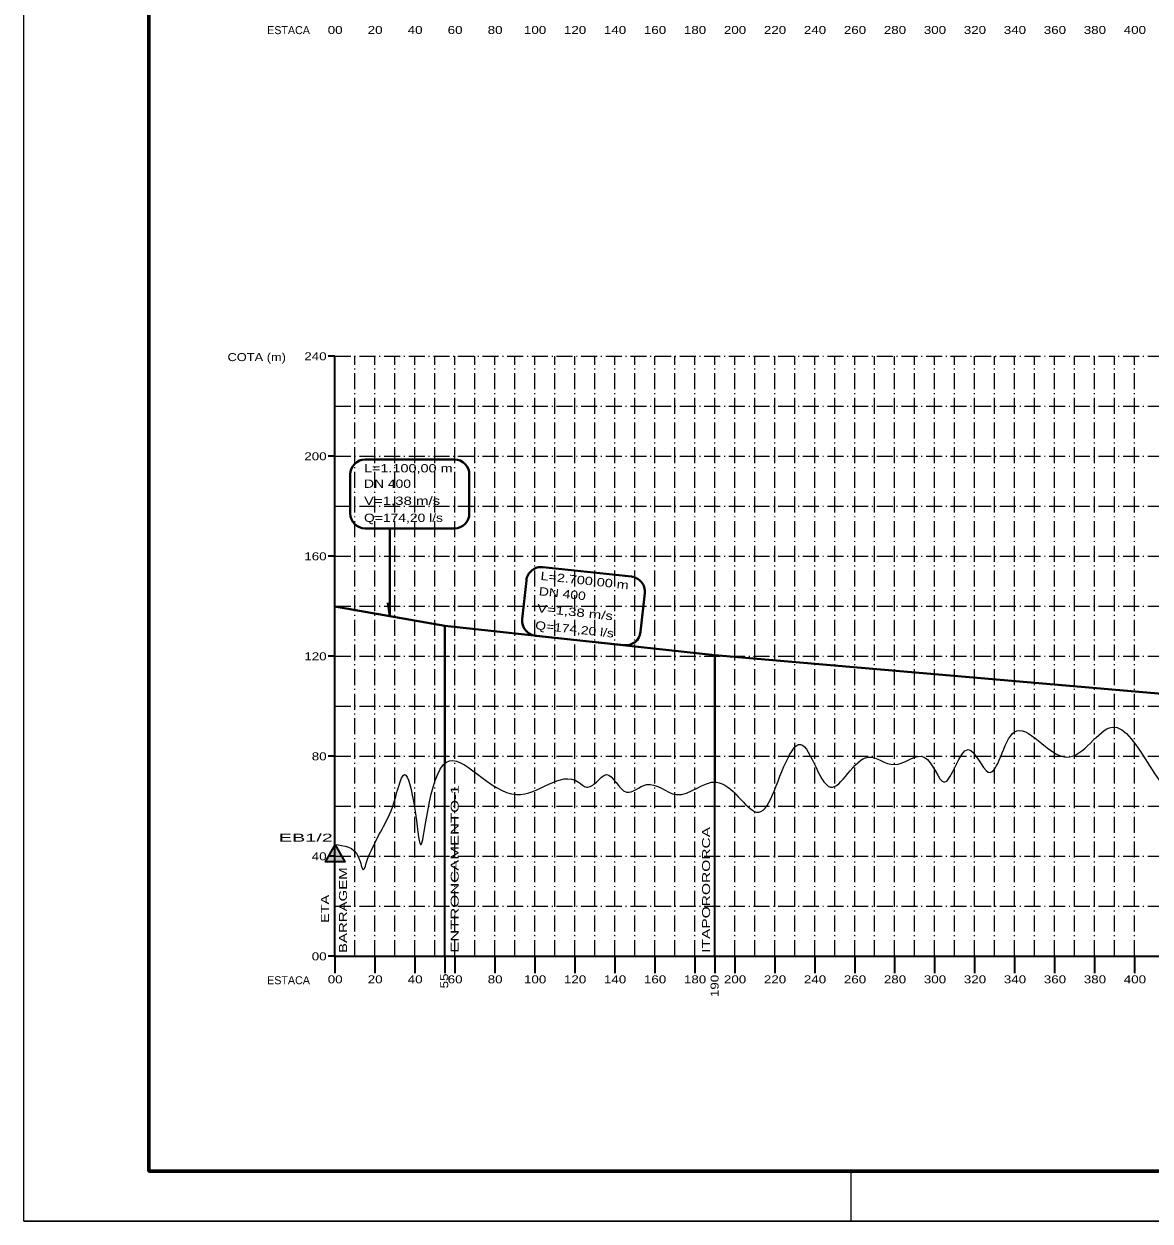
# Model space of a CAD drawing. Extents: x -4 to 42046, y -3 to 29697.
# Drawn here: x -4 to 11261, y -3 to 11967 of the extents above; entities that cross this region are included whole.
import ezdxf
from ezdxf.enums import TextEntityAlignment as Align

# ---------------------------------------------------------------- set-up
doc = ezdxf.new("R2010")
doc.units = 0
doc.header["$LTSCALE"] = 32
doc.linetypes.add('DOT_DASHED', pattern=[7.7, 5, -1.2, 0.3, -1.2])
for name, color, linetype, lineweight in [('1', 7, 'DOT_DASHED', 13), ('24', 7, 'Continuous', 35), ('56', 7, 'Continuous', 13), ('62', 7, 'Continuous', 13), ('63', 7, 'Continuous', 25), ('9', 7, 'Continuous', 40)]:
    doc.layers.add(name, color=color, linetype=linetype, lineweight=lineweight)

msp = doc.modelspace()

# ---------------------------------------------------------------- hatches: boundary and pattern name
at = {"layer": '62'}
msp.add_hatch(color=256, dxfattribs=at).paths.add_polyline_path([(3107.85, 3758.2), (3206.51, 3589.75), (3011.3, 3588.54)])

# ---------------------------------------------------------------- linework, layer by layer
at = {"layer": '1'}
for p, q in [((3105.77, 8646.17), (29145.77, 8646.17)), ((3305.77, 2646.17), (3305.77, 8646.17)), ((3505.77, 2646.17), (3505.77, 8646.17)), ((3705.77, 2646.17), (3705.77, 8646.17)), ((3905.77, 2646.17), (3905.77, 8646.17)), ((4105.77, 2646.17), (4105.77, 8646.17)), ((4305.77, 2646.17), (4305.77, 8646.17)), ((4505.77, 2646.17), (4505.77, 8646.17)), ((4705.77, 2646.17), (4705.77, 8646.17)), ((4905.77, 2646.17), (4905.77, 8646.17)), ((5105.77, 2646.17), (5105.77, 8646.17)), ((5305.77, 2646.17), (5305.77, 8646.17)), ((5505.77, 2646.17), (5505.77, 8646.17)), ((5705.77, 2646.17), (5705.77, 8646.17)), ((5905.77, 2646.17), (5905.77, 8646.17)), ((6105.77, 2646.17), (6105.77, 8646.17)), ((6305.77, 2646.17), (6305.77, 8646.17)), ((6505.77, 2646.17), (6505.77, 8646.17)), ((6705.77, 2646.17), (6705.77, 8646.17)), ((6905.77, 2646.17), (6905.77, 8646.17)), ((7105.77, 2646.17), (7105.77, 8646.17)), ((7305.77, 2646.17), (7305.77, 8646.17)), ((7505.77, 2646.17), (7505.77, 8646.17)), ((7705.77, 2646.17), (7705.77, 8646.17)), ((7905.77, 2646.17), (7905.77, 8646.17)), ((8105.77, 2646.17), (8105.77, 8646.17)), ((8305.77, 2646.17), (8305.77, 8646.17)), ((8505.77, 2646.17), (8505.77, 8646.17)), ((8705.77, 2646.17), (8705.77, 8646.17)), ((8905.77, 2646.17), (8905.77, 8646.17)), ((9105.77, 2646.17), (9105.77, 8646.17)), ((9305.77, 2646.17), (9305.77, 8646.17)), ((9505.77, 2646.17), (9505.77, 8646.17)), ((9705.77, 2646.17), (9705.77, 8646.17)), ((9905.77, 2646.17), (9905.77, 8646.17)), ((10105.77, 2646.17), (10105.77, 8646.17)), ((10305.77, 2646.17), (10305.77, 8646.17)), ((10505.77, 2646.17), (10505.77, 8646.17)), ((10705.77, 2646.17), (10705.77, 8646.17)), ((10905.77, 2646.17), (10905.77, 8646.17)), ((11105.77, 2646.17), (11105.77, 8646.17)), ((3105.77, 8146.17), (29145.77, 8146.17)), ((3105.77, 7646.17), (29145.77, 7646.17)), ((3105.77, 7146.17), (29145.77, 7146.17)), ((3105.77, 6646.17), (29145.77, 6646.17)), ((3105.77, 6146.17), (29145.77, 6146.17)), ((3105.77, 5646.17), (29145.77, 5646.17)), ((3105.77, 5146.17), (29145.77, 5146.17)), ((3105.77, 4646.17), (29145.77, 4646.17)), ((3105.77, 4146.17), (29145.77, 4146.17)), ((3105.77, 3646.17), (29145.77, 3646.17)), ((3105.77, 3146.17), (29145.77, 3146.17))]:
    msp.add_line(p, q, dxfattribs=at)
at = {"layer": '56'}
for points in [[(3442.18, 3641.64), (3562.37, 3886.04), (3682.37, 4136.04), (3802.37, 4461.04), (3902.37, 4136.04), (3962.37, 3761.04), (4222.37, 4586.04), (4922.37, 4261.04), (5542.37, 4386.04), (5622.37, 4336.04), (5722.37, 4386.04), (5822.37, 4461.04), (6022.37, 4286.04), (6222.37, 4361.04), (6522.37, 4261.04), (6922.37, 4386.04), (7322.37, 4086.04), (7642.37, 4636.04), (7742.37, 4761.04), (8062.37, 4336.04), (8442.37, 4636.04), (8702.37, 4561.04), (9002.37, 4636.04), (9202.37, 4386.04), (9442.37, 4711.04), (9642.37, 4486.04), (9902.37, 4886.04), (10422.37, 4636.04), (10882.37, 4936.04), (11642.37, 4261.04), (11942.37, 4511.04), (12062.37, 4386.04), (12382.37, 4411.04), (12982.37, 3611.04), (13192.37, 3711.04), (13592.37, 3636.04), (14032.37, 4011.04), (14532.37, 4661.04), (14732.37, 4386.04), (15932.37, 3461.04), (16672.37, 4386.04), (17705.77, 4596.17), (19279.94, 4205.37), (19682.37, 3586.04), (19842.37, 3761.04), (19942.37, 3836.04), (20242.37, 3636.04), (20442.37, 3786.04), (20542.37, 3636.04), (20942.37, 3636.04), (21942.37, 3386.04), (22342.37, 3086.04), (22942.37, 3886.04), (23242.37, 3511.04), (23362.37, 3711.04), (23862.37, 3011.04), (24002.37, 3136.04), (24202.37, 3061.04), (24402.37, 3136.04), (24882.37, 2886.04), (25102.37, 2836.04), (25362.37, 3011.04), (26082.37, 2836.04), (26222.37, 2886.04), (26322.37, 2836.04), (26502.37, 2961.04), (26702.37, 2836.04), (27202.37, 3011.04), (27602.37, 2836.04), (27762.37, 2961.04), (27862.37, 2886.04), (27982.37, 2936.04), (28182.37, 2811.04), (28342.37, 2886.04), (28742.37, 2836.04), (29145.65, 2836.26)], [(3102.37, 3761.04), (3342.37, 3636.04), (3392.37, 3511.04), (3429.87, 3604.79), (3442.18, 3641.64)]]:
    msp.add_spline(points, degree=3, dxfattribs=at)
at = {"layer": '62', "lineweight": 35}
for p, q in [((3105.77, 8646.17), (3037.5, 8646.17)), ((3101.57, 8646.17), (3105.77, 8646.17)), ((3105.77, 2646.17), (3105.77, 8646.17)), ((3101.57, 8396.17), (3105.77, 8396.17)), ((3101.57, 8146.17), (3105.77, 8146.17)), ((3101.57, 7896.17), (3105.77, 7896.17)), ((3105.77, 7646.17), (3037.5, 7646.17)), ((3101.57, 7646.17), (3105.77, 7646.17)), ((3101.57, 7396.17), (3105.77, 7396.17)), ((3101.57, 7146.17), (3105.77, 7146.17)), ((3101.57, 6896.17), (3105.77, 6896.17)), ((3105.77, 6646.17), (3037.5, 6646.17)), ((3101.57, 6646.17), (3105.77, 6646.17)), ((3101.57, 6396.17), (3105.77, 6396.17)), ((3101.57, 6146.17), (3105.77, 6146.17)), ((3101.57, 5896.17), (3105.77, 5896.17)), ((3105.77, 5646.17), (3037.5, 5646.17)), ((3101.57, 5646.17), (3105.77, 5646.17)), ((3101.57, 5396.17), (3105.77, 5396.17)), ((3101.57, 5146.17), (3105.77, 5146.17)), ((3101.57, 4896.17), (3105.77, 4896.17)), ((3105.77, 4646.17), (3037.5, 4646.17)), ((3101.57, 4646.17), (3105.77, 4646.17)), ((4205.77, 2646.17), (4205.77, 4585.53)), ((3101.57, 4396.17), (3105.77, 4396.17)), ((6905.77, 2646.17), (6905.77, 4384.84)), ((3101.57, 4146.17), (3105.77, 4146.17)), ((3101.57, 3896.17), (3105.77, 3896.17)), ((3105.77, 3646.17), (3037.5, 3646.17)), ((3101.57, 3646.17), (3105.77, 3646.17)), ((3101.57, 3396.17), (3105.77, 3396.17)), ((3101.57, 3146.17), (3105.77, 3146.17)), ((3101.57, 2896.17), (3105.77, 2896.17)), ((3105.77, 2646.17), (3037.5, 2646.17)), ((3105.77, 2646.17), (3105.77, 2475.48)), ((3105.77, 2646.17), (29145.77, 2646.17)), ((3505.77, 2646.17), (3505.77, 2475.48)), ((3905.77, 2646.17), (3905.77, 2475.48)), ((4205.77, 2646.17), (4205.77, 2475.48)), ((4305.77, 2646.17), (4305.77, 2475.48)), ((4705.77, 2646.17), (4705.77, 2475.48)), ((5105.77, 2646.17), (5105.77, 2475.48)), ((5505.77, 2646.17), (5505.77, 2475.48)), ((5905.77, 2646.17), (5905.77, 2475.48)), ((6305.77, 2646.17), (6305.77, 2475.48)), ((6705.77, 2646.17), (6705.77, 2475.48)), ((6905.77, 2646.17), (6905.77, 2475.48)), ((7105.77, 2646.17), (7105.77, 2475.48)), ((7505.77, 2646.17), (7505.77, 2475.48)), ((7905.77, 2646.17), (7905.77, 2475.48)), ((8305.77, 2646.17), (8305.77, 2475.48)), ((8705.77, 2646.17), (8705.77, 2475.48)), ((9105.77, 2646.17), (9105.77, 2475.48)), ((9505.77, 2646.17), (9505.77, 2475.48)), ((9905.77, 2646.17), (9905.77, 2475.48)), ((10305.77, 2646.17), (10305.77, 2475.48)), ((10705.77, 2646.17), (10705.77, 2475.48)), ((11105.77, 2646.17), (11105.77, 2475.48))]:
    msp.add_line(p, q, dxfattribs=at)
at = {"layer": '62'}
for p, q in [((3101.57, 8596.17), (3105.77, 8596.17)), ((3101.57, 8546.17), (3105.77, 8546.17)), ((3101.57, 8496.17), (3105.77, 8496.17)), ((3101.57, 8446.17), (3105.77, 8446.17)), ((3101.57, 8346.17), (3105.77, 8346.17)), ((3101.57, 8296.17), (3105.77, 8296.17)), ((3101.57, 8246.17), (3105.77, 8246.17)), ((3101.57, 8196.17), (3105.77, 8196.17)), ((3101.57, 8096.17), (3105.77, 8096.17)), ((3101.57, 8046.17), (3105.77, 8046.17)), ((3101.57, 7996.17), (3105.77, 7996.17)), ((3101.57, 7946.17), (3105.77, 7946.17)), ((3101.57, 7846.17), (3105.77, 7846.17)), ((3101.57, 7796.17), (3105.77, 7796.17)), ((3101.57, 7746.17), (3105.77, 7746.17)), ((3101.57, 7696.17), (3105.77, 7696.17)), ((3101.57, 7596.17), (3105.77, 7596.17)), ((3101.57, 7546.17), (3105.77, 7546.17)), ((3101.57, 7496.17), (3105.77, 7496.17)), ((3101.57, 7446.17), (3105.77, 7446.17)), ((3101.57, 7346.17), (3105.77, 7346.17)), ((3101.57, 7296.17), (3105.77, 7296.17)), ((3101.57, 7246.17), (3105.77, 7246.17)), ((3101.57, 7196.17), (3105.77, 7196.17)), ((3101.57, 7096.17), (3105.77, 7096.17)), ((3101.57, 7046.17), (3105.77, 7046.17)), ((3101.57, 6996.17), (3105.77, 6996.17)), ((3101.57, 6946.17), (3105.77, 6946.17)), ((3101.57, 6846.17), (3105.77, 6846.17)), ((3101.57, 6796.17), (3105.77, 6796.17)), ((3101.57, 6746.17), (3105.77, 6746.17)), ((3101.57, 6696.17), (3105.77, 6696.17)), ((3101.57, 6596.17), (3105.77, 6596.17)), ((3101.57, 6546.17), (3105.77, 6546.17)), ((3101.57, 6496.17), (3105.77, 6496.17)), ((3101.57, 6446.17), (3105.77, 6446.17)), ((3101.57, 6346.17), (3105.77, 6346.17)), ((3101.57, 6296.17), (3105.77, 6296.17)), ((3101.57, 6246.17), (3105.77, 6246.17)), ((3101.57, 6196.17), (3105.77, 6196.17)), ((3101.57, 6096.17), (3105.77, 6096.17)), ((3101.57, 6046.17), (3105.77, 6046.17)), ((3101.57, 5996.17), (3105.77, 5996.17)), ((3101.57, 5946.17), (3105.77, 5946.17)), ((3101.57, 5846.17), (3105.77, 5846.17)), ((3101.57, 5796.17), (3105.77, 5796.17)), ((3101.57, 5746.17), (3105.77, 5746.17)), ((3101.57, 5696.17), (3105.77, 5696.17)), ((3101.57, 5596.17), (3105.77, 5596.17)), ((3101.57, 5546.17), (3105.77, 5546.17)), ((3101.57, 5496.17), (3105.77, 5496.17)), ((3101.57, 5446.17), (3105.77, 5446.17)), ((3101.57, 5346.17), (3105.77, 5346.17)), ((3101.57, 5296.17), (3105.77, 5296.17)), ((3101.57, 5246.17), (3105.77, 5246.17)), ((3101.57, 5196.17), (3105.77, 5196.17)), ((3101.57, 5096.17), (3105.77, 5096.17)), ((3101.57, 5046.17), (3105.77, 5046.17)), ((3101.57, 4996.17), (3105.77, 4996.17)), ((3101.57, 4946.17), (3105.77, 4946.17)), ((3101.57, 4846.17), (3105.77, 4846.17)), ((3101.57, 4796.17), (3105.77, 4796.17)), ((3101.57, 4746.17), (3105.77, 4746.17)), ((3101.57, 4696.17), (3105.77, 4696.17)), ((3101.57, 4596.17), (3105.77, 4596.17)), ((3101.57, 4546.17), (3105.77, 4546.17)), ((3101.57, 4496.17), (3105.77, 4496.17)), ((3101.57, 4446.17), (3105.77, 4446.17)), ((3101.57, 4346.17), (3105.77, 4346.17)), ((3101.57, 4296.17), (3105.77, 4296.17)), ((3101.57, 4246.17), (3105.77, 4246.17)), ((3101.57, 4196.17), (3105.77, 4196.17)), ((3101.57, 4096.17), (3105.77, 4096.17)), ((3101.57, 4046.17), (3105.77, 4046.17)), ((3101.57, 3996.17), (3105.77, 3996.17)), ((3101.57, 3946.17), (3105.77, 3946.17)), ((3101.57, 3846.17), (3105.77, 3846.17)), ((3101.57, 3796.17), (3105.77, 3796.17)), ((3101.57, 3746.17), (3105.77, 3746.17)), ((3101.57, 3696.17), (3105.77, 3696.17)), ((3101.57, 3596.17), (3105.77, 3596.17)), ((3101.57, 3546.17), (3105.77, 3546.17)), ((3101.57, 3496.17), (3105.77, 3496.17)), ((3101.57, 3446.17), (3105.77, 3446.17)), ((3101.57, 3346.17), (3105.77, 3346.17)), ((3101.57, 3296.17), (3105.77, 3296.17)), ((3101.57, 3246.17), (3105.77, 3246.17)), ((3101.57, 3196.17), (3105.77, 3196.17)), ((3101.57, 3096.17), (3105.77, 3096.17)), ((3101.57, 3046.17), (3105.77, 3046.17)), ((3101.57, 2996.17), (3105.77, 2996.17)), ((3101.57, 2946.17), (3105.77, 2946.17)), ((3101.57, 2846.17), (3105.77, 2846.17)), ((3101.57, 2796.17), (3105.77, 2796.17)), ((3101.57, 2746.17), (3105.77, 2746.17)), ((3101.57, 2696.17), (3105.77, 2696.17))]:
    msp.add_line(p, q, dxfattribs=at)
at = {"layer": '62', "lineweight": 35}
msp.add_lwpolyline([(3107.85, 3758.2), (3206.51, 3589.75), (3011.3, 3588.54)], close=True, dxfattribs=at)
at = {"layer": '63'}
for p, q in [((-4.21, -2.97), (-4.21, 29697.03)), ((8270.8, -2.97), (8270.8, 497.03))]:
    msp.add_line(p, q, dxfattribs=at)
at = {"layer": '63', "lineweight": 60}
msp.add_line((41545.8, 497.03), (1245.8, 497.03), dxfattribs=at)
at = {"layer": '63'}
for points in [[(-4.21, -2.97), (42045.8, -2.97), (42045.8, 29697.03)], [(-4.21, -2.97), (42045.8, -2.97), (-4.21, -2.97)]]:
    msp.add_lwpolyline(points, dxfattribs=at)
at = {"layer": '63', "lineweight": 60}
msp.add_lwpolyline([(23554.57, 497.03), (1245.8, 497.03), (1245.8, 29197.03)], dxfattribs=at)
at = {"layer": '9'}
for p, q in [((3410.35, 7612.23), (4301.2, 7612.23)), ((3260.35, 7462.23), (3260.35, 7071.97)), ((4451.2, 7462.23), (4451.2, 7071.97)), ((3410.35, 6921.97), (4301.2, 6921.97)), ((5186.67, 6535.63), (6072.42, 6440.41)), ((5021.5, 6402.52), (4979.79, 6014.49)), ((6205.53, 6275.24), (6163.82, 5887.21)), ((4205.77, 4585.53), (4205.77, 5946.84)), ((5112.9, 5849.32), (5998.65, 5754.1)), ((6905.77, 4384.84), (6905.77, 5656.59))]:
    msp.add_line(p, q, dxfattribs=at)
for points in [[(3634.98, 6179.46), (3655.77, 6043.59), (3655.77, 6921.97)], [(3105.77, 6140.34), (4205.77, 5946.84), (6905.77, 5656.59), (17705.77, 4721.17), (19305.77, 4582.59), (20905.77, 4459.09), (29145.77, 3554.09)]]:
    msp.add_lwpolyline(points, dxfattribs=at)
for centre, start, end in [((3410.35, 7462.23), 90, 180), ((4301.2, 7462.23), 0, 90), ((3410.35, 7071.97), 180, 270), ((4301.2, 7071.97), 270, 0), ((5170.64, 6386.49), 83.86427, 173.86427), ((6056.39, 6291.27), 353.86427, 83.86427), ((5128.93, 5998.46), 173.86427, 263.86427), ((6014.68, 5903.24), 263.86427, 353.86427)]:
    msp.add_arc(centre, 150, start, end, dxfattribs=at)

# ---------------------------------------------------------------- texts
at = {"layer": '24'}
for p in [(2642.65, 11864.69), (2642.65, 2364.69)]:
    msp.add_text('ESTACA', height=80, dxfattribs=at).set_placement(p, align=Align.CENTER)
at = {"layer": '24', "width": 1.25}
for s, p in [('00', (3108.9, 11866.51)), ('20', (3508.9, 11866.51)), ('40', (3908.9, 11866.51)), ('60', (4308.9, 11866.51)), ('80', (4708.9, 11866.51)), ('100', (5108.9, 11866.51)), ('120', (5508.9, 11866.51)), ('140', (5908.9, 11866.51)), ('160', (6308.9, 11866.51)), ('180', (6708.9, 11866.51)), ('200', (7108.9, 11866.51)), ('220', (7508.9, 11866.51)), ('240', (7908.9, 11866.51)), ('260', (8308.9, 11866.51)), ('280', (8708.9, 11866.51)), ('300', (9108.9, 11866.51)), ('320', (9508.9, 11866.51)), ('340', (9908.9, 11866.51)), ('360', (10308.9, 11866.51)), ('380', (10708.9, 11866.51)), ('400', (11108.9, 11866.51)), ('00', (3109.27, 2373.89)), ('20', (3509.27, 2373.89)), ('40', (3909.27, 2373.89)), ('60', (4309.27, 2373.89)), ('80', (4709.27, 2373.89)), ('100', (5109.27, 2373.89)), ('120', (5509.27, 2373.89)), ('140', (5909.27, 2373.89)), ('160', (6309.27, 2373.89)), ('180', (6709.27, 2373.89)), ('200', (7109.27, 2373.89)), ('220', (7509.27, 2373.89)), ('240', (7909.27, 2373.89)), ('260', (8309.27, 2373.89)), ('280', (8709.27, 2373.89)), ('300', (9109.27, 2373.89)), ('320', (9509.27, 2373.89)), ('340', (9909.27, 2373.89)), ('360', (10309.27, 2373.89)), ('380', (10709.27, 2373.89)), ('400', (11109.27, 2373.89))]:
    msp.add_text(s, height=80, dxfattribs=at).set_placement(p, align=Align.CENTER)
at = {"layer": '24'}
for s, width, p in [('COTA (m)', 1.2, (2616.74, 8595.49)), ('240', 1.25, (3023.55, 8603.64)), ('200', 1.25, (3023.55, 7603.64)), ('160', 1.25, (3023.55, 6603.64)), ('120', 1.25, (3023.55, 5603.64)), ('80', 1.25, (3023.55, 4603.64)), ('40', 1.25, (3023.55, 3603.64)), ('00', 1.25, (3023.55, 2603.64))]:
    msp.add_text(s, height=80, dxfattribs=dict(at, width=width)).set_placement(p, align=Align.RIGHT)
for s, width, p in [('ENTRONCAMENTO-1', 1.55, (4344.86, 2679.09)), ('ITAPORORORCA', 1.45, (6859.47, 2679.09)), ('BARRAGEM', 1.4, (3227.45, 2676.95)), ('ETA', 1.35, (3046.75, 2978.27))]:
    msp.add_text(s, height=80, rotation=90, dxfattribs=dict(at, width=width)).set_placement(p)
at = {"layer": '24', "width": 1.85}
msp.add_text('EB1/2', height=80, dxfattribs=at).set_placement((2545.69, 3790.11))
at = {"layer": '24', "width": 1.25}
for s, p in [('55', (4239.95, 2397.86)), ('190', (6944.27, 2347.96))]:
    msp.add_text(s, height=80, rotation=90, dxfattribs=at).set_placement(p, align=Align.CENTER)
at = {"layer": '9'}
for s, width, p in [('L=1.100,00 m', 1.3, (3397.47, 7482.77)), ('DN 400', 1.25, (3397.47, 7328.27)), ('V=1,38 m/s', 1.35, (3397.47, 7157.68)), ('Q=174,20 l/s', 1.25, (3397.47, 6987.09))]:
    msp.add_text(s, height=82.98, dxfattribs=dict(at, width=width)).set_placement(p)
for s, width, p in [('L=2.700,00 m', 1.3, (5160.03, 6408.28)), ('DN 400', 1.25, (5143.52, 6254.67)), ('V=1,38 m/s', 1.35, (5125.28, 6085.06)), ('Q=174,20 l/s', 1.25, (5107.05, 5915.45))]:
    msp.add_text(s, height=82.98, rotation=353.864, dxfattribs=dict(at, width=width)).set_placement(p)

doc.saveas('drawing.dxf')
